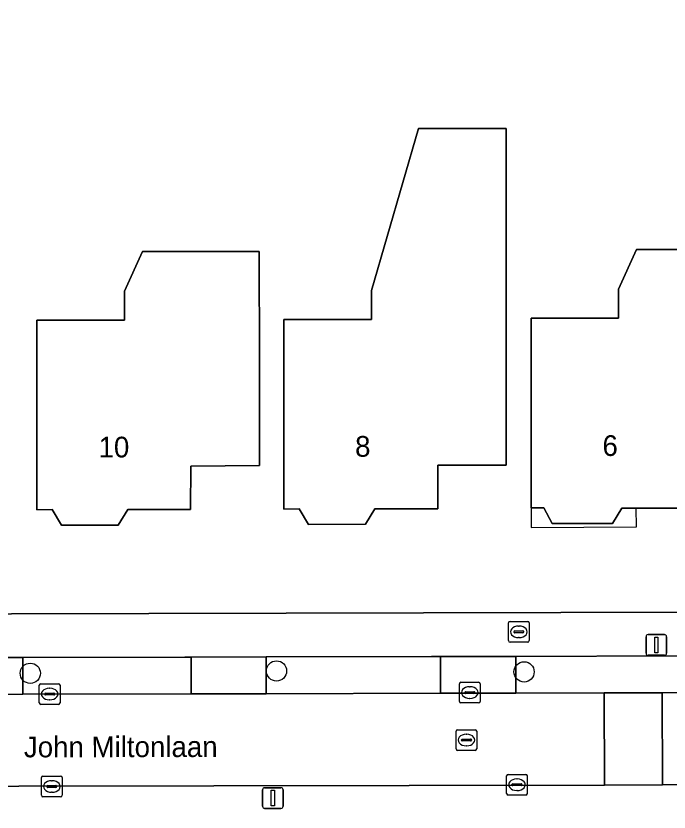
# Model space of a CAD drawing. Extents: x 160455 to 162082, y 388339 to 389736.
# Drawn here: x 160925.99 to 160957.57, y 388380.96 to 388419.44 of the extents above; entities that cross this region are included whole.
import ezdxf

# ---------------------------------------------------------------- set-up
doc = ezdxf.new("R2010")
doc.units = 0
for name, color, linetype in [('IMGEO_Boom', 7, 'Continuous'), ('IMGEO_Brandkraan', 7, 'Continuous'), ('IMGEO_Erf', 7, 'Continuous'), ('IMGEO_Groenvoorziening', 7, 'Continuous'), ('IMGEO_Kolk', 7, 'Continuous'), ('IMGEO_Lichtmast', 7, 'Continuous'), ('IMGEO_Openbare_ruimte_label', 7, 'Continuous'), ('IMGEO_Pand', 7, 'Continuous'), ('IMGEO_Pand_nummerreeks', 7, 'Continuous'), ('IMGEO_Pand_overbouw', 7, 'Continuous'), ('IMGEO_Parkeervlak_open', 7, 'Continuous'), ('IMGEO_Rijbaan_lokaal_open', 7, 'Continuous'), ('IMGEO_Rioolput', 7, 'Continuous'), ('IMGEO_Voetpad_open', 7, 'Continuous')]:
    doc.layers.add(name, color=color, linetype=linetype)

msp = doc.modelspace()

# ---------------------------------------------------------------- linework, layer by layer
at = {"layer": 'IMGEO_Boom'}
for centre in [(160926.69, 388387.669), (160938.595, 388387.781), (160950.563, 388387.737)]:
    msp.add_circle(centre, 0.489, dxfattribs=at)
at = {"layer": 'IMGEO_Brandkraan'}
for p, q in [((160949.811, 388389.248), (160949.811, 388390.1)), ((160949.886, 388390.174), (160950.738, 388390.174)), ((160950.299, 388389.954), (160950.324, 388389.954)), ((160950.812, 388390.1), (160950.812, 388389.248)), ((160950.07, 388389.668), (160950.07, 388389.68)), ((160950.508, 388389.631), (160950.11, 388389.631)), ((160950.113, 388389.717), (160950.511, 388389.717)), ((160950.554, 388389.68), (160950.554, 388389.668)), ((160950.738, 388389.174), (160949.886, 388389.174)), ((160950.322, 388389.394), (160950.297, 388389.394))]:
    msp.add_line(p, q, dxfattribs=at)
for points in [[(160949.811, 388389.248), (160949.811, 388390.1)], [(160949.886, 388390.174), (160950.738, 388390.174)], [(160950.812, 388390.1), (160950.812, 388389.248)], [(160950.738, 388389.174), (160949.886, 388389.174)]]:
    msp.add_lwpolyline(points, dxfattribs=at)
for centre, radius, start, end in [((160949.888, 388390.098), 0.0765, 91.552, 178.448), ((160949.888, 388390.098), 0.0765, 91.552, 178.448), ((160950.736, 388390.098), 0.0765, 1.552, 88.448), ((160950.736, 388390.098), 0.0765, 1.552, 88.448), ((160950.11, 388389.677), 0.0403, 85.8775, 175.7526), ((160950.107, 388389.667), 0.0366, 178.938, 274.7102), ((160950.511, 388389.674), 0.043, 264.8664, 352.4533), ((160950.515, 388389.679), 0.0386, 1.7309, 96.639), ((160949.888, 388389.25), 0.0765, 181.552, 268.448), ((160949.888, 388389.25), 0.0765, 181.552, 268.448), ((160950.736, 388389.25), 0.0765, 271.552, 358.448), ((160950.736, 388389.25), 0.0765, 271.552, 358.448)]:
    msp.add_arc(centre, radius, start, end, dxfattribs=at)
for centre, major_axis, ratio, start_param, end_param in [((160950.298, 388389.674), (-0.387, 0.002), 0.722429, 4.712389, 7.853982), ((160950.323, 388389.674), (-0.39, 0.002), 0.717154, 1.570796, 4.712389)]:
    msp.add_ellipse(centre, major_axis=major_axis, ratio=ratio, start_param=start_param, end_param=end_param, dxfattribs=at)
at = {"layer": 'IMGEO_Erf'}
msp.add_lwpolyline([(160892.553, 388390.467), (160985.556, 388390.695), (161000.936, 388390.733), (161010.95, 388390.757), (161015.566, 388395.957), (161015.408, 388449.738)], dxfattribs=at)
for points in [[(160949.701, 388402.733), (160949.702, 388397.733), (160946.401, 388397.726), (160946.39, 388395.626), (160943.35, 388395.619), (160942.893, 388394.87), (160940.133, 388394.863), (160939.691, 388395.611), (160938.951, 388395.609), (160938.95, 388400.609), (160938.95, 388404.769), (160943.18, 388404.77), (160943.18, 388406.17), (160945.451, 388413.996), (160949.699, 388413.997), (160949.7, 388408.091)], [(160937.764, 388402.708), (160937.765, 388397.708), (160934.452, 388397.676), (160934.441, 388395.591), (160931.401, 388395.585), (160930.944, 388394.836), (160928.194, 388394.831), (160927.742, 388395.579), (160927.014, 388395.577), (160927.013, 388400.577), (160927.013, 388404.737), (160931.243, 388404.738), (160931.243, 388406.138), (160932.113, 388408.059), (160937.763, 388408.059)], [(160955.998, 388408.15), (160961.648, 388408.15), (160961.649, 388402.76), (160961.65, 388397.76), (160958.333, 388397.728), (160958.335, 388395.643), (160955.99, 388395.651), (160955.286, 388395.654), (160954.844, 388394.906), (160951.924, 388394.916), (160951.526, 388395.666), (160950.899, 388395.668), (160950.898, 388400.668), (160950.898, 388404.828), (160955.128, 388404.829), (160955.128, 388406.229)]]:
    msp.add_lwpolyline(points, close=True, dxfattribs=at)
at = {"layer": 'IMGEO_Groenvoorziening'}
msp.add_lwpolyline([(161011.549, 388363.67), (161011.529, 388382.357), (161007.757, 388382.366), (161000, 388382.351), (160957.248, 388382.271), (160954.448, 388382.266), (160907.226, 388382.178), (160892.537, 388382.121), (160876.614, 388382.064), (160819.396, 388381.852), (160819.474, 388361.158)], dxfattribs=at)
at = {"layer": 'IMGEO_Kolk'}
for p, q in [((160927.201, 388387.165), (160928.053, 388387.165)), ((160947.437, 388386.311), (160947.437, 388387.163)), ((160947.512, 388387.237), (160948.364, 388387.237)), ((160948.438, 388387.163), (160948.438, 388386.311)), ((160927.126, 388386.239), (160927.126, 388387.091)), ((160927.614, 388386.945), (160927.639, 388386.945)), ((160928.127, 388387.091), (160928.127, 388386.239)), ((160947.739, 388386.78), (160948.137, 388386.78)), ((160947.925, 388387.017), (160947.95, 388387.017)), ((160927.385, 388386.659), (160927.385, 388386.671)), ((160927.823, 388386.622), (160927.425, 388386.622)), ((160927.428, 388386.708), (160927.826, 388386.708)), ((160927.869, 388386.671), (160927.869, 388386.659)), ((160947.696, 388386.731), (160947.696, 388386.743)), ((160948.134, 388386.694), (160947.736, 388386.694)), ((160947.948, 388386.457), (160947.923, 388386.457)), ((160948.18, 388386.743), (160948.18, 388386.731)), ((160928.053, 388386.165), (160927.201, 388386.165)), ((160927.637, 388386.385), (160927.612, 388386.385)), ((160948.364, 388386.237), (160947.512, 388386.237)), ((160927.229, 388381.772), (160927.229, 388382.624)), ((160927.304, 388382.698), (160928.156, 388382.698)), ((160928.23, 388382.624), (160928.23, 388381.772)), ((160949.719, 388381.855), (160949.719, 388382.707)), ((160949.794, 388382.781), (160950.646, 388382.781)), ((160950.207, 388382.561), (160950.232, 388382.561)), ((160950.72, 388382.707), (160950.72, 388381.855)), ((160927.488, 388382.192), (160927.488, 388382.204)), ((160927.531, 388382.241), (160927.929, 388382.241)), ((160927.717, 388382.478), (160927.742, 388382.478)), ((160927.972, 388382.204), (160927.972, 388382.192)), ((160949.978, 388382.275), (160949.978, 388382.287)), ((160950.416, 388382.238), (160950.018, 388382.238)), ((160950.021, 388382.324), (160950.419, 388382.324)), ((160950.462, 388382.287), (160950.462, 388382.275)), ((160927.926, 388382.155), (160927.528, 388382.155)), ((160927.74, 388381.918), (160927.715, 388381.918)), ((160950.646, 388381.781), (160949.794, 388381.781)), ((160950.23, 388382.001), (160950.205, 388382.001)), ((160928.156, 388381.698), (160927.304, 388381.698))]:
    msp.add_line(p, q, dxfattribs=at)
for points in [[(160927.201, 388387.165), (160928.053, 388387.165)], [(160947.437, 388386.311), (160947.437, 388387.163)], [(160947.512, 388387.237), (160948.364, 388387.237)], [(160948.438, 388387.163), (160948.438, 388386.311)], [(160927.126, 388386.239), (160927.126, 388387.091)], [(160928.127, 388387.091), (160928.127, 388386.239)], [(160928.053, 388386.165), (160927.201, 388386.165)], [(160948.364, 388386.237), (160947.512, 388386.237)], [(160927.229, 388381.772), (160927.229, 388382.624)], [(160927.304, 388382.698), (160928.156, 388382.698)], [(160928.23, 388382.624), (160928.23, 388381.772)], [(160949.719, 388381.855), (160949.719, 388382.707)], [(160949.794, 388382.781), (160950.646, 388382.781)], [(160950.72, 388382.707), (160950.72, 388381.855)], [(160950.646, 388381.781), (160949.794, 388381.781)], [(160928.156, 388381.698), (160927.304, 388381.698)]]:
    msp.add_lwpolyline(points, dxfattribs=at)
for centre, radius, start, end in [((160927.203, 388387.089), 0.0765, 91.552, 178.448), ((160927.203, 388387.089), 0.0765, 91.552, 178.448), ((160928.051, 388387.089), 0.0765, 1.552, 88.448), ((160928.051, 388387.089), 0.0765, 1.552, 88.448), ((160947.514, 388387.161), 0.0765, 91.552, 178.448), ((160947.514, 388387.161), 0.0765, 91.552, 178.448), ((160948.362, 388387.161), 0.0765, 1.552, 88.448), ((160948.362, 388387.161), 0.0765, 1.552, 88.448), ((160947.736, 388386.74), 0.0403, 85.8775, 175.7526), ((160948.141, 388386.742), 0.0386, 1.7309, 96.639), ((160927.425, 388386.668), 0.0403, 85.8775, 175.7526), ((160927.422, 388386.658), 0.0366, 178.938, 274.7102), ((160927.826, 388386.665), 0.043, 264.8664, 352.4533), ((160927.83, 388386.67), 0.0386, 1.7309, 96.639), ((160947.733, 388386.73), 0.0366, 178.938, 274.7102), ((160948.137, 388386.737), 0.043, 264.8664, 352.4533), ((160927.203, 388386.241), 0.0765, 181.552, 268.448), ((160927.203, 388386.241), 0.0765, 181.552, 268.448), ((160928.051, 388386.241), 0.0765, 271.552, 358.448), ((160928.051, 388386.241), 0.0765, 271.552, 358.448), ((160947.514, 388386.313), 0.0765, 181.552, 268.448), ((160947.514, 388386.313), 0.0765, 181.552, 268.448), ((160948.362, 388386.313), 0.0765, 271.552, 358.448), ((160948.362, 388386.313), 0.0765, 271.552, 358.448), ((160927.306, 388382.622), 0.0765, 91.552, 178.448), ((160927.306, 388382.622), 0.0765, 91.552, 178.448), ((160928.154, 388382.622), 0.0765, 1.552, 88.448), ((160928.154, 388382.622), 0.0765, 1.552, 88.448), ((160949.796, 388382.705), 0.0765, 91.552, 178.448), ((160949.796, 388382.705), 0.0765, 91.552, 178.448), ((160950.644, 388382.705), 0.0765, 1.552, 88.448), ((160950.644, 388382.705), 0.0765, 1.552, 88.448), ((160927.528, 388382.201), 0.0403, 85.8775, 175.7526), ((160927.525, 388382.191), 0.0366, 178.938, 274.7102), ((160927.929, 388382.198), 0.043, 264.8664, 352.4533), ((160927.933, 388382.203), 0.0386, 1.7309, 96.639), ((160950.018, 388382.284), 0.0403, 85.8775, 175.7526), ((160950.015, 388382.274), 0.0366, 178.938, 274.7102), ((160950.419, 388382.281), 0.043, 264.8664, 352.4533), ((160950.423, 388382.286), 0.0386, 1.7309, 96.639), ((160949.796, 388381.857), 0.0765, 181.552, 268.448), ((160949.796, 388381.857), 0.0765, 181.552, 268.448), ((160950.644, 388381.857), 0.0765, 271.552, 358.448), ((160950.644, 388381.857), 0.0765, 271.552, 358.448), ((160927.306, 388381.774), 0.0765, 181.552, 268.448), ((160927.306, 388381.774), 0.0765, 181.552, 268.448), ((160928.154, 388381.774), 0.0765, 271.552, 358.448), ((160928.154, 388381.774), 0.0765, 271.552, 358.448)]:
    msp.add_arc(centre, radius, start, end, dxfattribs=at)
for centre, major_axis, ratio, start_param, end_param in [((160927.613, 388386.665), (-0.387, 0.002), 0.722429, 4.712389, 7.853982), ((160927.638, 388386.665), (-0.39, 0.002), 0.717154, 1.570796, 4.712389), ((160947.924, 388386.737), (-0.387, 0.002), 0.722429, 4.712389, 7.853982), ((160947.949, 388386.737), (-0.39, 0.002), 0.717154, 1.570796, 4.712389), ((160950.206, 388382.281), (-0.387, 0.002), 0.722429, 4.712389, 7.853982), ((160950.231, 388382.281), (-0.39, 0.002), 0.717154, 1.570796, 4.712389), ((160927.716, 388382.198), (-0.387, 0.002), 0.722429, 4.712389, 7.853982), ((160927.741, 388382.198), (-0.39, 0.002), 0.717154, 1.570796, 4.712389)]:
    msp.add_ellipse(centre, major_axis=major_axis, ratio=ratio, start_param=start_param, end_param=end_param, dxfattribs=at)
at = {"layer": 'IMGEO_Lichtmast'}
for p, q in [((160956.559, 388389.539), (160957.349, 388389.539)), ((160957.349, 388389.539), (160956.559, 388389.539)), ((160956.459, 388388.639), (160956.459, 388389.439)), ((160956.459, 388389.439), (160956.459, 388388.639)), ((160957.449, 388389.439), (160957.449, 388388.639)), ((160957.449, 388388.639), (160957.449, 388389.439)), ((160957.349, 388388.539), (160956.559, 388388.539)), ((160956.559, 388388.539), (160957.349, 388388.539)), ((160937.92, 388381.239), (160937.92, 388382.039)), ((160937.92, 388382.039), (160937.92, 388381.239)), ((160938.02, 388382.139), (160938.81, 388382.139)), ((160938.81, 388382.139), (160938.02, 388382.139)), ((160938.91, 388382.039), (160938.91, 388381.239)), ((160938.91, 388381.239), (160938.91, 388382.039)), ((160938.81, 388381.139), (160938.02, 388381.139)), ((160938.02, 388381.139), (160938.81, 388381.139))]:
    msp.add_line(p, q, dxfattribs=at)
for points in [[(160956.879, 388389.414), (160957.029, 388389.414), (160957.029, 388388.664), (160956.879, 388388.664), (160956.879, 388389.414)], [(160938.34, 388382.014), (160938.49, 388382.014), (160938.49, 388381.264), (160938.34, 388381.264), (160938.34, 388382.014)]]:
    msp.add_lwpolyline(points, dxfattribs=at)
for centre, start, end in [((160956.559, 388389.439), 90, 180), ((160956.559, 388389.439), 90, 180), ((160957.349, 388389.439), 0, 90), ((160957.349, 388389.439), 360, 90), ((160956.559, 388388.639), 180, 270), ((160956.559, 388388.639), 180, 270), ((160957.349, 388388.639), 270, 0), ((160957.349, 388388.639), 270, 0), ((160938.02, 388382.039), 90, 180), ((160938.02, 388382.039), 90, 180), ((160938.81, 388382.039), 0, 90), ((160938.81, 388382.039), 360, 90), ((160938.02, 388381.239), 180, 270), ((160938.02, 388381.239), 180, 270), ((160938.81, 388381.239), 270, 0), ((160938.81, 388381.239), 270, 0)]:
    msp.add_arc(centre, 0.1, start, end, dxfattribs=at)
at = {"layer": 'IMGEO_Pand'}
for points in [[(160949.701, 388402.733), (160949.7, 388408.091), (160949.699, 388413.997), (160945.451, 388413.996), (160943.18, 388406.17), (160943.18, 388404.77), (160938.95, 388404.769), (160938.95, 388400.609), (160938.951, 388395.609), (160939.691, 388395.611), (160940.133, 388394.863), (160942.893, 388394.87), (160943.35, 388395.619), (160946.39, 388395.626), (160946.401, 388397.726), (160949.702, 388397.733)], [(160937.764, 388402.708), (160937.763, 388408.059), (160932.113, 388408.059), (160931.243, 388406.138), (160931.243, 388404.738), (160927.013, 388404.737), (160927.013, 388400.577), (160927.014, 388395.577), (160927.742, 388395.579), (160928.194, 388394.831), (160930.944, 388394.836), (160931.401, 388395.585), (160934.441, 388395.591), (160934.452, 388397.676), (160937.765, 388397.708)], [(160955.99, 388395.651), (160958.335, 388395.643), (160958.333, 388397.728), (160961.65, 388397.76), (160961.649, 388402.76), (160961.648, 388408.15), (160955.998, 388408.15), (160955.128, 388406.229), (160955.128, 388404.829), (160950.898, 388404.828), (160950.898, 388400.668), (160950.899, 388395.668), (160951.526, 388395.666), (160951.924, 388394.916), (160954.844, 388394.906), (160955.286, 388395.654)]]:
    msp.add_lwpolyline(points, close=True, dxfattribs=at)
at = {"layer": 'IMGEO_Pand_overbouw'}
msp.add_lwpolyline([(160955.99, 388395.651), (160955.286, 388395.654), (160954.844, 388394.906), (160951.924, 388394.916), (160951.526, 388395.666), (160950.899, 388395.668), (160950.901, 388394.719), (160955.999, 388394.743)], close=True, dxfattribs=at)
at = {"layer": 'IMGEO_Parkeervlak_open'}
for points in [[(160926.331, 388388.437), (160922.578, 388388.436), (160922.582, 388386.647), (160926.335, 388386.656)], [(160934.463, 388388.451), (160934.166, 388388.45), (160926.331, 388388.437), (160926.335, 388386.656), (160934.467, 388386.674)], [(160938.087, 388388.46), (160934.463, 388388.451), (160934.467, 388386.674), (160938.091, 388386.682)], [(160946.517, 388388.481), (160946.081, 388388.48), (160938.087, 388388.46), (160938.091, 388386.682), (160946.521, 388386.701)], [(160950.16, 388388.487), (160946.517, 388388.481), (160946.521, 388386.701), (160950.164, 388386.709)], [(160970.427, 388388.545), (160970.051, 388388.544), (160961.899, 388388.522), (160957.983, 388388.509), (160950.16, 388388.487), (160950.164, 388386.709), (160954.438, 388386.719), (160957.238, 388386.725), (160970.431, 388386.755)]]:
    msp.add_lwpolyline(points, close=True, dxfattribs=at)
at = {"layer": 'IMGEO_Rijbaan_lokaal_open'}
msp.add_lwpolyline([(161009.082, 388386.84), (161008.977, 388386.84), (161000, 388386.821), (160986.032, 388386.79), (160981.802, 388386.78), (160973.98, 388386.762), (160970.431, 388386.755), (160957.238, 388386.725), (160957.248, 388382.271), (161000, 388382.351), (161007.757, 388382.366), (161011.529, 388382.357), (161013.643, 388382.351), (161016.228, 388382.343)], dxfattribs=at)
for points in [[(160954.438, 388386.719), (160950.164, 388386.709), (160946.521, 388386.701), (160938.091, 388386.682), (160934.467, 388386.674), (160926.335, 388386.656), (160922.582, 388386.647), (160914.27, 388386.628), (160910.602, 388386.62), (160906.478, 388386.611), (160893.201, 388386.594), (160892.777, 388386.603), (160892.518, 388386.606), (160892.537, 388382.121), (160907.226, 388382.178), (160954.448, 388382.266)], [(160957.248, 388382.271), (160957.238, 388386.725), (160954.438, 388386.719), (160954.448, 388382.266)]]:
    msp.add_lwpolyline(points, close=True, dxfattribs=at)
at = {"layer": 'IMGEO_Rioolput'}
for p, q in [((160947.275, 388384.017), (160947.275, 388384.869)), ((160947.35, 388384.943), (160948.202, 388384.943)), ((160948.276, 388384.869), (160948.276, 388384.017)), ((160947.577, 388384.486), (160947.975, 388384.486)), ((160947.763, 388384.723), (160947.788, 388384.723)), ((160947.534, 388384.437), (160947.534, 388384.449)), ((160947.972, 388384.4), (160947.574, 388384.4)), ((160947.786, 388384.163), (160947.761, 388384.163)), ((160948.018, 388384.449), (160948.018, 388384.437)), ((160948.202, 388383.943), (160947.35, 388383.943))]:
    msp.add_line(p, q, dxfattribs=at)
for points in [[(160947.275, 388384.017), (160947.275, 388384.869)], [(160947.35, 388384.943), (160948.202, 388384.943)], [(160948.276, 388384.869), (160948.276, 388384.017)], [(160948.202, 388383.943), (160947.35, 388383.943)]]:
    msp.add_lwpolyline(points, dxfattribs=at)
for centre, radius, start, end in [((160947.352, 388384.867), 0.0765, 91.552, 178.448), ((160947.352, 388384.867), 0.0765, 91.552, 178.448), ((160948.2, 388384.867), 0.0765, 1.552, 88.448), ((160948.2, 388384.867), 0.0765, 1.552, 88.448), ((160947.574, 388384.446), 0.0403, 85.8775, 175.7526), ((160947.979, 388384.448), 0.0386, 1.7309, 96.639), ((160947.571, 388384.436), 0.0366, 178.938, 274.7102), ((160947.975, 388384.443), 0.043, 264.8664, 352.4533), ((160947.352, 388384.019), 0.0765, 181.552, 268.448), ((160947.352, 388384.019), 0.0765, 181.552, 268.448), ((160948.2, 388384.019), 0.0765, 271.552, 358.448), ((160948.2, 388384.019), 0.0765, 271.552, 358.448)]:
    msp.add_arc(centre, radius, start, end, dxfattribs=at)
for centre, major_axis, ratio, start_param, end_param in [((160947.762, 388384.443), (-0.387, 0.002), 0.722429, 4.712389, 7.853982), ((160947.787, 388384.443), (-0.39, 0.002), 0.717154, 1.570796, 4.712389)]:
    msp.add_ellipse(centre, major_axis=major_axis, ratio=ratio, start_param=start_param, end_param=end_param, dxfattribs=at)
at = {"layer": 'IMGEO_Voetpad_open'}
for points in [[(161010.95, 388390.757), (161000.936, 388390.733), (160985.556, 388390.695), (160892.553, 388390.467), (160888.372, 388388.454)], [(160895.659, 388388.377), (160910.347, 388388.4), (160910.598, 388388.401), (160914.266, 388388.412), (160922.259, 388388.436), (160922.578, 388388.436), (160926.331, 388388.437), (160934.166, 388388.45), (160934.463, 388388.451), (160938.087, 388388.46), (160946.081, 388388.48), (160946.517, 388388.481), (160950.16, 388388.487), (160957.983, 388388.509), (160961.899, 388388.522), (160970.051, 388388.544), (160970.427, 388388.545), (160973.976, 388388.559), (160981.798, 388388.571), (160986.028, 388388.584), (161000, 388388.607), (161006.032, 388388.617)]]:
    msp.add_lwpolyline(points, dxfattribs=at)

# ---------------------------------------------------------------- texts
at = {"layer": 'IMGEO_Openbare_ruimte_label'}
msp.add_text('John Miltonlaan', height=1, rotation=0.1146, dxfattribs=at).set_placement((160926.382, 388383.606))
at = {"layer": 'IMGEO_Pand_nummerreeks'}
for s, rotation, p in [('10', 0.108, (160929.991, 388398.102)), ('8', 0.1309, (160942.394, 388398.137)), ('6', 359.8074, (160954.351, 388398.176))]:
    msp.add_text(s, height=1, rotation=rotation, dxfattribs=at).set_placement(p)

doc.saveas('drawing.dxf')
